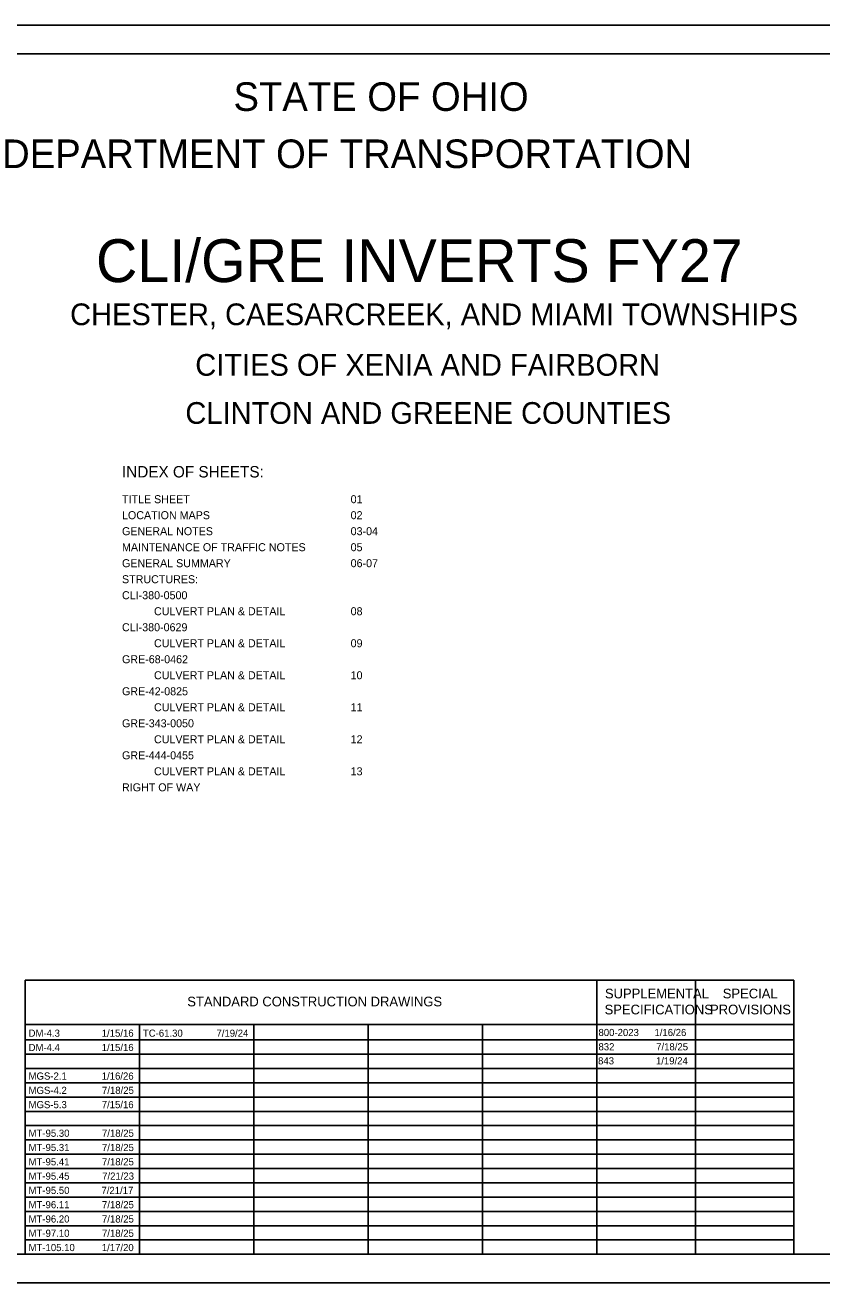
# Model space of a CAD drawing. Extents: x 0 to 44.3, y 0 to 22.
# Drawn here: x 10.15 to 24.09, y 0 to 22 of the extents above; entities that cross this region are included whole.
import ezdxf

# ---------------------------------------------------------------- set-up
doc = ezdxf.new("R2010")
doc.units = 0
for name, color, linetype in [('SC_Scratch1', 7, 'Continuous'), ('SH_Border', 7, 'Continuous'), ('SH_Cut_Line', 7, 'Continuous'), ('SH_Data', 7, 'Continuous'), ('SH_Text', 7, 'Continuous')]:
    doc.layers.add(name, color=color, linetype=linetype)

msp = doc.modelspace()

# ---------------------------------------------------------------- linework, layer by layer
at = {"layer": 'SH_Border'}
msp.add_lwpolyline([(1.5, 21.5), (33.5, 21.5), (33.5, 0.5), (1.5, 0.5)], close=True, dxfattribs=at)
at = {"layer": 'SH_Cut_Line'}
msp.add_lwpolyline([(0, 0), (34, 0), (34, 22), (0, 22)], close=True, dxfattribs=at)
at = {"layer": 'SH_Data'}
for p, q in [((10.15, 5.292), (23.6, 5.292)), ((10.15, 0.5), (10.15, 5.292)), ((20.15, 0.5), (20.15, 5.292)), ((21.875, 0.5), (21.875, 5.292)), ((23.6, 0.5), (23.6, 5.292)), ((10.15, 4.521), (23.6, 4.521)), ((12.15, 0.5), (12.15, 4.521)), ((14.15, 0.5), (14.15, 4.521)), ((16.15, 0.5), (16.15, 4.521)), ((18.15, 0.5), (18.15, 4.521)), ((10.15, 4.25), (23.6, 4.25)), ((10.15, 4), (23.6, 4)), ((10.15, 3.75), (23.6, 3.75)), ((10.15, 3.5), (23.6, 3.5)), ((10.15, 3.25), (23.6, 3.25)), ((10.15, 3), (23.6, 3)), ((10.15, 2.75), (23.6, 2.75)), ((10.15, 2.5), (23.6, 2.5)), ((10.15, 2.25), (23.6, 2.25)), ((10.15, 2), (23.6, 2)), ((10.15, 1.75), (23.6, 1.75)), ((10.15, 1.5), (23.6, 1.5)), ((10.15, 1.25), (23.6, 1.25)), ((10.15, 1), (23.6, 1)), ((10.15, 0.75), (23.6, 0.75))]:
    msp.add_line(p, q, dxfattribs=at)

# ---------------------------------------------------------------- texts
at = {"layer": 'SC_Scratch1'}
for s, p in [('DM-4.3', (10.21, 4.305)), ('1/15/16', (11.49, 4.305)), ('TC-61.30', (12.21, 4.305)), ('7/19/24', (13.497, 4.305)), ('1/15/16', (11.49, 4.055)), ('DM-4.4', (10.21, 4.055)), ('MGS-2.1', (10.21, 3.555)), ('1/16/26', (11.49, 3.555)), ('MGS-4.2', (10.21, 3.305)), ('7/18/25', (11.494, 3.305)), ('MGS-5.3', (10.21, 3.055)), ('7/15/16', (11.49, 3.055)), ('MT-95.30', (10.21, 2.555)), ('7/18/25', (11.494, 2.555)), ('MT-95.31', (10.21, 2.305)), ('7/18/25', (11.494, 2.305)), ('MT-95.41', (10.21, 2.055)), ('7/18/25', (11.494, 2.055)), ('MT-95.45', (10.21, 1.805)), ('7/21/23', (11.497, 1.805)), ('MT-95.50', (10.21, 1.555)), ('7/21/17', (11.485, 1.555)), ('MT-96.11', (10.21, 1.305)), ('7/18/25', (11.494, 1.305)), ('MT-96.20', (10.21, 1.055)), ('7/18/25', (11.494, 1.055)), ('MT-97.10', (10.21, 0.805)), ('7/18/25', (11.494, 0.805)), ('MT-105.10', (10.21, 0.555)), ('1/17/20', (11.491, 0.555))]:
    msp.add_text(s, height=0.125, dxfattribs=at).set_placement(p)
at = {"layer": 'SH_Text'}
for s, height, p in [('STATE OF OHIO', 0.5, (13.795, 20.5)), ('DEPARTMENT OF TRANSPORTATION', 0.5, (9.747, 19.5)), ('CLI/GRE INVERTS FY27', 0.75, (11.389, 17.505)), ('CHESTER, CAESARCREEK, AND MIAMI TOWNSHIPS', 0.38, (10.937, 16.752)), ('CITIES OF XENIA AND FAIRBORN', 0.38, (13.126, 15.867)), ('CLINTON AND GREENE COUNTIES', 0.38, (12.953, 15.026)), ('INDEX OF SHEETS:', 0.2, (11.844, 14.088)), ('TITLE SHEET', 0.14, (11.844, 13.638)), ('01', 0.14, (15.844, 13.638)), ('LOCATION MAPS', 0.14, (11.844, 13.358)), ('02', 0.14, (15.844, 13.358)), ('GENERAL NOTES', 0.14, (11.844, 13.078)), ('03-04', 0.14, (15.844, 13.078)), ('MAINTENANCE OF TRAFFIC NOTES', 0.14, (11.844, 12.798)), ('05', 0.14, (15.844, 12.798)), ('GENERAL SUMMARY', 0.14, (11.844, 12.518)), ('06-07', 0.14, (15.844, 12.518)), ('STRUCTURES:', 0.14, (11.844, 12.238)), ('CLI-380-0500', 0.14, (11.844, 11.958)), ('CULVERT PLAN & DETAIL', 0.14, (12.404, 11.678)), ('08', 0.14, (15.844, 11.678)), ('CLI-380-0629', 0.14, (11.844, 11.398)), ('CULVERT PLAN & DETAIL', 0.14, (12.404, 11.118)), ('09', 0.14, (15.844, 11.118)), ('GRE-68-0462 ', 0.14, (11.844, 10.838)), ('CULVERT PLAN & DETAIL', 0.14, (12.404, 10.558)), ('10', 0.14, (15.844, 10.558)), ('GRE-42-0825', 0.14, (11.844, 10.278)), ('CULVERT PLAN & DETAIL', 0.14, (12.404, 9.998)), ('11', 0.14, (15.844, 9.998)), ('GRE-343-0050', 0.14, (11.844, 9.718)), ('CULVERT PLAN & DETAIL', 0.14, (12.404, 9.438)), ('12', 0.14, (15.844, 9.438)), ('GRE-444-0455', 0.14, (11.844, 9.158)), ('CULVERT PLAN & DETAIL', 0.14, (12.404, 8.878)), ('13', 0.14, (15.844, 8.878)), ('RIGHT OF WAY', 0.14, (11.844, 8.598)), ('SUPPLEMENTAL', 0.17, (20.293, 4.976)), ('SPECIAL', 0.17, (22.354, 4.976)), ('STANDARD CONSTRUCTION DRAWINGS', 0.17, (12.986, 4.836)), ('SPECIFICATIONS', 0.17, (20.287, 4.696)), ('PROVISIONS', 0.17, (22.132, 4.696)), ('800-2023', 0.125, (20.18, 4.317)), ('1/16/26', 0.125, (21.159, 4.317)), ('832', 0.125, (20.18, 4.067)), ('7/18/25', 0.125, (21.189, 4.067)), ('843', 0.125, (20.173, 3.821)), ('1/19/24', 0.125, (21.185, 3.821))]:
    msp.add_text(s, height=height, dxfattribs=at).set_placement(p)

doc.saveas('drawing.dxf')
